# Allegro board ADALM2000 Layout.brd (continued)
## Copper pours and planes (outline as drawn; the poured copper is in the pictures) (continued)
-6V0_A on TOP: 42.9,16.46 42.9,17.35 43.79,17.35 43.79,20.01 48.74,20.01 48.74,18.11 46.89,18.11 46.89,18.72 45.59,18.72 45.59,18.11 45.57,18.11 45.57,16.46
-6V0_A on TOP: 51.03,11.12 57,11.12 57.76,10.36 58.9,10.36 58.9,14.04 58.39,14.04 57.76,13.41 51.03,13.41
-6V0_A on BOTTOM: 21.69,6.04 23.34,6.04 23.34,7.95 21.69,7.95
-6V0_A on BOTTOM: 24.61,40.21 24.61,37.92 24.99,37.92 25.12,37.79 27.28,37.79 27.28,38.68 27.66,39.06 27.66,40.21
-6V0_A on BOTTOM: 51.15,11.12 57,11.12 57.12,11.25 59.03,11.25 59.03,13.41 51.15,13.41
-6V0_A on L8_PWR: 13.94,5.53 13.94,41.09 27.91,41.09 27.91,27.19 21.05,27.19 21.05,14.68 33.31,14.68 33.31,20.77 51.59,20.77 57.12,15.25 57.12,10.3 41.43,10.3 39.85,8.71 25.06,8.71 25.06,5.53
-6V0_AWG_A on BOTTOM: 24.48,34.62 26.26,34.62 26.39,34.74 26.39,37.35 24.48,37.35
-6V0_AWG_A on L3_PWR: 22.83,27.76 22.83,36.33 33.63,36.33 33.63,27.76
-6V0_SC_A on TOP: 14.96,50.49 14.96,48.71 16.86,48.71 16.86,50.49
-6V0_SC_A on BOTTOM: 32,46.17 32,47.85 31.85,47.85 31.85,48.51 32.1,48.51 32.1,48.56 33.86,48.56 34.01,48.71 35.15,48.71 35.15,47.7 34.36,46.91 32.76,46.91 32.76,46.17
-6V0_SC_A on BOTTOM: 17.75,49.73 17.75,48.84 20.8,48.84 20.8,49.98 19.02,49.98 18.77,49.73
-6V0_SC_A on BOTTOM: 32.61,37.09 32.61,37.98 32.04,38.55 27.66,38.55 27.66,37.67 28.61,37.67 29.18,37.09
-6V0_SC_A on L3_PWR: 22.83,36.97 22.83,46.17 13.94,46.17 13.94,50.3 22.83,50.3 22.83,54.75 28.55,54.75 28.55,48.08 33.63,48.08 33.63,36.97
-6V0_USR_A on TOP (solid shape): 11.59,6.04 12.99,6.04 13,6.04 13.31,6.04 13.43,5.92 13.43,5.47 13.37,5.38 13.27,5.39 13.2,5.43 13.13,5.45 12.72,5.45 12.58,5.39 12.52,5.24 12.52,5.03 12.32,5.03 12.32,5.24 12.26,5.39 12.11,5.45 11.71,5.45 11.56,5.39 11.5,5.24 11.5,5.03 11.28,5.03 11.28,6.04 11.58,6.04
-6V0_USR_A on BOTTOM (solid shape): 13.82,4.9 13.54,4.9 13.54,5.33 13.48,5.47 13.33,5.53 12.77,5.53 12.63,5.47 12.57,5.33 12.57,4.9 12.39,4.9 12.39,5.33 12.33,5.47 12.19,5.53 11.63,5.53 11.49,5.47 11.43,5.33 11.43,4.9 11.15,4.9 11.15,6.04 13.82,6.04
-6V0_USR_A on BOTTOM: 19.91,6.04 21.31,6.04 21.31,7.69 19.91,7.69
-6V0_USR_A on L6_SIG: 10.77,4.9 21.56,4.9 21.56,8.58 10.77,8.58
GND on TOP: 95.1,45.67 95.1,48.41 95.2,48.41 95.2,48.89 94.79,48.89 94.71,48.97 94.71,49.73 93.83,49.73 93.83,53.29 97.38,53.29 97.38,49.73 96.49,49.73 96.49,48.71 96.43,48.65 96.43,49.71 96.02,49.71 96.02,48.39 96.24,48.39 96.24,45.67 ; 2 cut-outs
GND on TOP: outline of 92 points within 0.64,0.64 108.5,68.7 ; 150 cut-outs
GND on BOTTOM: 102.21,4.02 79.2,1.56 56.08,0.64 56.08,6.28 52.28,10.08 48.48,6.28 48.48,0.68 26.97,1.69 5.56,4.05 5.56,5.66 5.55,5.66 4.42,6.68 3.28,5.66 3.27,5.66 3.27,4.38 1.96,4.58 0.64,4.78 0.64,15.69 0.61,15.69 0.61,15.82 0.73,15.82 0.73,53.29 0.64,53.29 0.64,64.55 1.89,64.75 3.15,64.94 5.69,65.31 27.03,67.65 48.48,68.66 48.48,63.06 52.28,59.26 56.08,63.06 56.08,68.7 75.11,68.05 94.08,66.36 94.08,57.1 98.72,57.1 100.62,55.19 100.62,51.89 102.53,49.98 102.53,40.52 101.57,39.57 101.57,32.84 105.07,29.35 108.5,29.35 108.5,16.08 108.5,8.6 107.49,5.87 104.95,4.43 104.75,4.4 104.75,5.53 103.48,6.8 102.21,5.53 ; 182 cut-outs
GND on L2_GND: 104.08,4.29 80.14,1.63 56.08,0.64 56.08,6.28 52.28,10.08 48.48,6.28 48.48,0.68 24.49,1.9 0.64,4.78 0.64,64.55 24.49,67.44 48.48,68.66 48.48,63.06 52.28,59.26 56.08,63.06 56.08,68.7 75.11,68.05 94.08,66.36 94.08,57.1 98.72,57.1 100.62,55.19 100.62,51.89 102.53,49.98 102.53,40.52 101.57,39.57 101.57,36.01 104.32,36.01 104.32,34.11 101.57,34.11 101.57,32.84 105.07,29.35 108.5,29.35 108.5,15.52 108.5,8.6 107.49,5.87 104.95,4.43
GND on L3_PWR: 86.97,46.81 86.97,62.68 56.06,62.68 56.07,62.87 56.08,63.06 56.08,68.7 75.11,68.05 94.08,66.36 94.08,57.1 98.71,57.1 100.74,55.06 100.62,55.06 100.62,51.89 102.53,49.98 102.53,46.81
GND on L3_PWR: 38.14,1 19.33,2.38 0.64,4.78 0.64,64.55 24.49,67.44 48.48,68.66 48.48,65.22 33.95,65.22 33.95,60.14 13.31,60.14 13.31,45.54 22.2,45.54 22.2,27.76 15.85,27.76 15.85,5.85 38.14,5.85
GND on L3_PWR: 77.44,1.43 66.77,0.87 56.08,0.64 56.08,6.28 55.52,8.26 54,9.66 71.73,9.66 71.73,22.68 77.44,22.68
GND on L4_GND, L7_GND, L9_GND: 104.08,4.29 80.14,1.63 56.08,0.64 56.08,6.28 52.28,10.08 48.48,6.28 48.48,0.68 24.49,1.9 0.64,4.78 0.64,64.55 24.49,67.44 48.48,68.66 48.48,63.06 52.28,59.26 56.08,63.06 56.08,68.7 75.11,68.05 94.08,66.36 94.08,57.1 98.72,57.1 100.62,55.19 100.62,51.89 102.53,49.98 102.53,40.52 101.57,39.57 101.57,32.84 105.07,29.35 108.5,29.35 108.5,15.52 108.5,8.6 107.49,5.87 104.95,4.43
GND on L5_SIG: 108.5,8.6 107.49,5.87 104.95,4.43 104.08,4.29 80.14,1.63 56.08,0.64 56.08,6.28 52.28,10.08 48.48,6.28 48.48,0.68 39.45,0.94 30.43,1.44 20.37,2.27 10.34,3.41 5.48,4.06 0.64,4.78 0.64,9.98 1.12,9.98 1.12,13.92 0.64,13.92 0.64,64.55 24.49,67.44 48.48,68.66 48.48,63.06 52.28,59.26 56.08,63.06 56.08,68.7 75.11,68.05 94.08,66.36 94.08,57.1 98.72,57.1 100.62,55.19 100.62,51.89 102.53,49.98 102.53,40.52 101.57,39.57 101.57,32.84 105.07,29.35 108.5,29.35 108.5,19.82 ; 63 cut-outs
GND on L8_PWR: 48.48,0.68 24.49,1.9 0.64,4.78 0.64,64.55 24.49,67.44 48.48,68.66 48.48,63.06 52.28,59.26 56.08,63.06 56.08,68.7 67.72,68.43 79.35,67.77 79.35,61.41 59.98,61.41 55.03,56.46 55.03,52.33 66.33,52.33 66.33,46.17 49.5,46.17 49.5,57.1 45.19,61.41 20.93,61.41 20.93,41.73 13.31,41.73 13.31,4.9 25.69,4.9 25.69,8.07 40.11,8.07 41.7,9.66 50.55,9.66 49.04,8.26 48.48,6.28
PGND on TOP: 105,40.97 105,39.32 106.4,39.32 106.4,41.09 105.13,41.09
PGND on TOP: 105.7,58.94 105.7,59.19 106.59,60.08 106.59,60.91 106.65,60.97 108.49,60.97 108.49,58.94
PGND on TOP: 103.16,43.13 103.16,50.37 101.26,52.27 101.26,55.32 98.91,57.67 94.91,57.67 94.91,60.97 97.45,60.97 97.45,59.51 98.52,58.43 99.1,58.43 100.56,59.89 100.56,60.14 104.62,64.21 108.08,60.75 107.8,60.46 106.72,60.46 105.13,62.05 104.49,62.05 102.02,59.57 101.95,59.57 101.06,58.68 101.06,57.86 101.89,57.03 101.89,52.84 102.08,52.65 103.73,52.65 104.43,51.95 104.43,45.79 104.94,45.79 104.94,45.1 104.62,44.78 104.62,43.13
PGND on TOP: 102.84,32.46 103.73,32.46 104.11,32.84 104.11,33.6 102.97,33.6 102.72,33.35 102.72,32.59
PGND on BOTTOM: 105.38,29.92 102.72,32.59 102.72,33.6 105,33.6 105,37.67 104.49,38.17 104.49,40.08 104.75,40.33 104.75,41.73 105.45,42.43 106.91,42.43 106.91,46.11 106.65,46.37 105.89,46.37 105.64,46.11 104.37,46.11 104.3,46.05 104.3,43.13 103.16,43.13 103.16,50.3 101.26,52.21 101.26,55.32 98.91,57.67 94.91,57.67 94.91,65.22 102.72,65.22 106.84,61.1 107.41,61.1 108.49,60.02 108.49,55.89 106.65,55.89 106.65,55.51 106.46,55.32 106.46,48.21 107.16,47.51 108.43,47.51 108.43,39.82 106.97,39.82 106.46,39.32 106.46,29.92 ; 3 cut-outs
PGND on L2_GND: 103.16,40.14 103.16,50.3 101.26,52.21 101.26,55.32 98.91,57.67 94.91,57.67 94.91,65.22 102.72,65.22 106.84,61.1 107.41,61.1 108.49,60.02 108.49,55.89 106.65,55.89 106.65,55.37 106.54,55.11 106.5,54.82 106.81,54.07 107.56,53.76 107.61,53.76 107.61,51.13 107.56,51.13 106.81,50.82 106.5,50.07 106.81,49.32 107.56,49.01 108.43,49.01 108.43,39.82 106.97,39.82 106.46,39.32 106.46,29.92 105.38,29.92 102.72,32.59 102.72,33.6 105.7,33.6 105.7,36.27 105.07,36.9 102.21,36.9 102.21,39.19
PGND on L4_GND: 103.16,40.14 103.16,50.3 101.26,52.21 101.26,55.32 98.91,57.67 94.91,57.67 94.91,65.22 102.72,65.22 106.84,61.1 107.41,61.1 108.49,60.02 108.49,55.89 106.65,55.89 106.65,55.37 106.54,55.11 106.5,54.82 106.81,54.07 107.56,53.76 107.61,53.76 107.61,51.13 107.56,51.13 106.81,50.82 106.5,50.07 106.81,49.32 107.56,49.01 108.43,49.01 108.43,39.82 106.97,39.82 106.46,39.32 106.46,29.92 105.38,29.92 102.72,32.59 102.72,33.6 105,33.6 105,36.07 104.16,36.9 102.21,36.9 102.21,39.19
PGND on L7_GND, L9_GND: 103.16,40.14 103.16,50.3 101.26,52.21 101.26,55.32 98.91,57.67 94.91,57.67 94.91,65.22 102.72,65.22 106.84,61.1 107.41,61.1 108.49,60.02 108.49,55.89 106.65,55.89 106.65,55.37 106.54,55.11 106.5,54.82 106.81,54.07 107.56,53.76 107.61,53.76 107.61,51.13 107.56,51.13 106.81,50.82 106.5,50.07 106.81,49.32 107.56,49.01 108.43,49.01 108.43,39.82 106.97,39.82 106.46,39.32 106.46,29.92 105.38,29.92 102.72,32.59 102.72,33.6 105,33.6 105,36.07 104.16,36.9 102.21,36.9 102.21,39.19
VCCPINT on TOP: 80.87,44.78 80.87,43.63 83.03,41.48 84.55,41.48 84.55,44.52 84.3,44.78
VCCPINT on BOTTOM: 84.55,47.32 84.55,43.63 84.05,43.13 84.05,41.09 81.95,41.09 80.87,42.17 80.87,45.54 81.38,46.05 81.38,47.32
VCCPINT on L3_PWR: 71.73,23.31 71.73,46.17 91.73,46.17 91.73,34.24 88.56,31.07 88.56,27.26 84.61,23.31
VIN on TOP: 93.19,50.87 93.19,49.35 92.81,48.97 89.25,48.97 89.25,50.87 ; 1 cut-out
VIN on TOP: 83.41,51.38 84.43,51.38 84.81,51.76 88.11,51.76 88.11,53.16 82.78,53.16 82.78,52.02
VIN on TOP: 99.55,31.56 98.78,32.33 97.7,32.33 97.7,31.63 98.66,30.67
VIN on TOP: 97.89,50.87 101.57,50.87 102.21,50.24 102.21,48.97 98.4,48.97 97.89,49.48 ; 1 cut-out
VIN on TOP: 78.33,51.38 77.7,51.38 77.32,51.76 73.12,51.76 73.12,53.16 78.97,53.16 78.97,52.02
VIN on TOP: 85.44,63.57 86.33,62.68 91.29,62.68 91.67,62.3 93.95,62.3 93.95,65.22 87.48,65.22 86.59,66.11 83.28,66.11 83.28,63.57
VIN on L6_SIG: 106.65,22.68 97.13,32.2 97.13,48.71 97.76,49.35 97.76,51.25 101.19,51.25 102.21,50.24 102.21,47.38 99.29,47.38 99.29,42.11 101.57,39.82 101.57,32.84 105.07,29.35 108.3,29.35 108.3,9.79 106.65,9.79
VIN on L8_PWR: 82.84,48.71 82.84,51.57 73.32,51.57 73.32,54.75 66.33,54.75 66.33,52.97 55.66,52.97 55.66,56.21 60.23,60.78 79.98,60.78 79.98,65.61 90.33,65.61 94.08,61.86 94.08,57.1 98.72,57.1 100.62,55.19 100.62,51.91 102.53,50.01 102.53,48.71
VIN_5V_USB_DATA on TOP: 105.13,59.51 103.73,60.91 104.56,61.73 104.94,61.73 106.14,60.53 106.14,60.21 105.45,59.51 ; 2 cut-outs
VIN_5V_USB_DATA on TOP: 102.33,36.71 102.33,39.32 103.22,40.21 104.75,40.21 104.75,38.55 103.73,37.54 103.73,36.97 103.86,36.84 103.86,35.76 103.29,35.76
VIN_5V_USB_DATA on BOTTOM: 103.99,38.94 103.99,37.03 103.48,36.52 102.33,36.52 102.33,38.17 103.1,38.94
VIN_5V_USB_DATA on L8_PWR: 102.21,36.65 102.21,39.06 103.16,40.01 103.16,50.27 101.26,52.17 101.26,58.43 103.92,61.1 107.41,61.1 108.5,60.01 108.5,57.47 108.5,55.88 107.56,55.88 106.81,55.57 106.5,54.82 106.81,54.07 107.56,53.76 108.5,53.76 108.5,51.13 107.56,51.13 106.81,50.82 106.5,50.07 106.81,49.32 107.56,49.01 108.5,49.01 108.5,38.1 107.56,38.1 106.81,37.79 106.5,37.04 106.52,36.84 106.58,36.65
VIN_5V_USB_POWER on TOP: 102.21,53.16 102.21,57.35 101.38,58.18 101.38,58.56 102.14,59.32 102.21,59.32 104.05,57.48 104.05,53.67 103.54,53.16 ; 2 cut-outs
VIN_5V_USB_POWER on TOP: 104.87,46.11 106.78,46.11 106.78,47.38 105.38,47.38 104.87,46.87
VIN_5V_USB_POWER on BOTTOM: 102.21,54.18 103.54,54.18 103.54,55.51 102.21,55.51
VIN_5V_USB_POWER on L3_PWR: 105.32,29.98 102.72,32.59 102.72,33.6 104.94,33.6 104.94,36.65 102.21,36.65 102.21,39.06 103.16,40.01 103.16,50.24 101.26,52.15 101.26,55.7 101.01,55.7 98.97,57.73 94.71,57.73 94.71,66.29 99.4,65.7 104.08,65.04 104.95,64.9 107.49,63.47 108.5,60.73 108.5,57.47 108.5,55.88 107.56,55.88 106.81,55.57 106.5,54.82 106.81,54.07 107.56,53.76 108.5,53.76 108.5,51.13 107.56,51.13 106.81,50.82 106.5,50.07 106.81,49.32 107.56,49.01 108.5,49.01 108.5,38.1 107.56,38.1 106.81,37.79 106.5,37.04 106.81,36.29 107.56,35.98 108.5,35.98 108.5,33.35 107.56,33.35 106.81,33.04 106.5,32.29 106.81,31.54 107.56,31.23 108.5,31.23 108.5,29.98
(no net) on TOP: 13.43,5.03 11.28,5.03 11.28,6.04 13.31,6.04 13.43,5.92
(no net) on TOP: 15.72,12.01 19.98,12.01 19.98,13.47 15.72,13.47
(no net) on TOP: 13.69,11.12 11.66,11.12 11.66,12.14 13.43,12.14 13.69,11.88
(no net) on TOP: 15.72,6.3 18.51,6.3 18.51,7.57 15.72,7.57
(no net) on BOTTOM: 10.77,11 13.94,11 13.94,12.27 10.77,12.27
(no net) on BOTTOM: 16.36,6.42 18.9,6.42 18.9,7.57 16.36,7.57
(no net) on BOTTOM: 11.15,4.9 13.82,4.9 13.82,6.04 11.15,6.04
(no net) on BOTTOM: 16.61,12.01 18.9,12.01 18.9,13.28 16.74,13.28 16.36,12.9 16.36,12.27
(no net) on L6_SIG: outline of 252 points within 0.64,0.64 108.5,68.7 ; 11 cut-outs
REF_1V2 on BOTTOM: 33.95,24.08 31.21,24.08 31.21,26.36 32.23,26.36 32.48,26.62 33.95,26.62
REF_1V2_SC on BOTTOM: 41.37,23.31 41.37,25.35 40.49,25.35 40.49,26.49 38.83,26.49 38.83,25.35 38.33,25.35 38.33,23.31
UNNAMED_16_ADP5074_I189_SW on TOP: 56.11,17.98 65.63,17.98 65.63,12.77 62.71,12.77 62.71,15.06 58.01,15.06 56.11,16.96
UNNAMED_16_ADP7182V2_I221_VOUT on TOP: 43.28,18.11 41.25,18.11 41.25,20.52 43.28,20.52
UNNAMED_16_CAP_I199_N1 on TOP: 59.41,10.36 62.2,10.36 62.2,14.3 59.41,14.3
UNNAMED_37_ADP237X_I231_SW on TOP: 36.04,2.23 36.04,9.85 36.93,10.74 37.18,10.74 37.95,9.98 39.09,9.98 39.09,2.23
UNNAMED_37_ADP1614_I262_SW1 on TOP: 40.61,7.57 40.61,1.98 42.52,1.98 42.52,6.17 45.06,6.17 45.57,6.68 45.57,7.57
UNNAMED_37_CAP_I212_N1 on TOP: 32.61,13.41 32.61,20.01 29.94,20.01 29.94,15.44 28.67,15.44 28.67,13.41
UNNAMED_37_CAP_I212_N1 on BOTTOM: 32.61,14.81 30.33,14.81 30.33,20.65 32.61,20.65
UNNAMED_37_CAP_I222_N2 on TOP: 34.52,2.23 30.71,2.23 30.71,8.46 28.55,10.61 28.55,12.14 34.52,12.14
UNNAMED_37_CAP_I315_N1 on TOP: 43.41,10.04 40.36,10.04 40.36,12.9 42.14,12.9 42.14,12.46 43.41,11.19
UNNAMED_38_ADP2114_I358_SW1 on TOP: 96.75,49.54 97.31,49.54 98.52,48.33 98.52,42.62 96.75,42.62 ; 1 cut-out
UNNAMED_38_ADP2114_I358_SW3 on TOP: 94.46,42.62 92.81,42.62 92.81,48.42 93.61,49.22 94.46,49.22
UNNAMED_38_ADP2114_I447_SW1 on TOP: 82.01,51.76 82.01,45.29 83.67,45.29 83.67,50.75 82.65,51.76
UNNAMED_38_ADP2114_I447_SW3 on TOP: 79.73,51.51 79.73,49.73 79.98,49.48 79.98,47.44 75.92,47.44 75.92,48.59 76.43,49.1 78.33,49.1 78.33,51 78.84,51.51
UNNAMED_38_CAP_I379_N1 on TOP: 101.83,46.3 99.41,46.3 99.41,41.09 101.83,41.09
UNNAMED_38_CAP_I379_N1 on BOTTOM: 99.41,39.95 101.95,39.95 102.46,40.46 102.46,44.14 99.41,44.14
UNNAMED_38_CAP_I457_N1 on TOP: 73.38,43.76 76.3,43.76 77.19,44.65 79.35,44.65 79.98,45.29 79.98,46.68 76.05,46.68 75.54,47.19 73.38,47.19
UNNAMED_38_CAP_I457_N1 on BOTTOM: 73.38,43.76 76.68,43.76 76.68,47.01 73.38,47.01
UNNAMED_45_ADP198_I317_VOUT on TOP: 103.22,41.6 103.22,42.62 105.13,42.62 105.13,45.79 106.78,45.79 106.78,41.6
UNNAMED_45_ADP198_I317_VOUT on BOTTOM: 104.68,43 106.53,43 106.53,45.73 104.68,45.73
UNNAMED_45_CAP_I416_N1 on TOP: 98.65,58.87 100.65,60.87 99.92,61.61 99.92,61.8 101.19,63.07 101.57,63.07 102.21,62.43 104.11,64.34 103.35,65.1 102.84,65.1 102.72,65.22 94.84,65.22 94.91,64.94 94.91,62.11 97.25,62.11 97.89,61.48 97.89,59.64 ; 4 cut-outs
UNNAMED_45_CN5P3SHLD_I255_N6 on TOP: 106.02,30.17 106.02,36.33 105.76,36.59 105.76,38.68 106.65,39.57 106.65,40.97 107.92,40.97 107.92,40.08 108.5,39.5 108.5,38.1 107.56,38.1 106.81,37.79 106.5,37.04 106.81,36.29 107.56,35.98 108.5,35.98 108.5,33.35 107.56,33.35 106.81,33.04 106.5,32.29 106.81,31.54 107.56,31.23 108.5,31.23 108.5,30.28 108.3,30.28 108.3,30.17
UNNAMED_45_CN5P3SHLD_I256_N6 on TOP: 108.5,58.49 108.5,55.88 107.56,55.88 106.81,55.57 106.5,54.82 106.81,54.07 107.56,53.76 108.5,53.76 108.5,51.13 107.56,51.13 106.81,50.82 106.5,50.07 106.81,49.32 107.56,49.01 108.43,49.01 108.43,47.95 106.02,47.95 106.02,54.94 105.7,55.26 105.7,58.49
USB_VBUS_OTG on TOP: 99.41,39.44 99.41,37.6 101.76,37.6 101.76,39.44
USB_VBUS_OTG on BOTTOM: 99.16,38.3 99.67,37.79 101.32,37.79 102.21,38.68 102.21,38.94 99.54,38.94 99.16,38.55
VTT_0P75 on TOP: 102.3,28.75 103.92,27.13 104.9,28.12 103.02,30.01 102.39,29.38 102.66,29.11
VTT_0P75 on BOTTOM: 104.62,18.36 98.82,24.16 93.64,18.99 94.63,18 98.53,21.89 101.74,18.67 100.08,17.01 99.18,17.01 97.44,15.26 99.2,13.51 100.79,15.1 100.79,16.09 101.4,16.7 103.57,16.7 104.55,15.73 104.31,15.5 105.03,14.78 103.27,13.02 102.91,13.02 99.23,9.34 99.95,8.62 101.03,8.62 103.81,11.4 105.07,11.4 107.67,14 107.67,26.49 105.76,28.39 103.99,28.39 103.16,29.22 102.33,28.39 102.33,27.38 105.38,24.33 105.38,18.62 105.13,18.36

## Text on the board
Board Geometry/Soldermask Bottom: SOLDERMASK SECONDARY | 08-      -06
Ref Des/Silkscreen Bottom: SECONDARY SIDE | SILKSCREEN SECONDARY | 08-      -05
User.Comments: CR_1_1 | 5.    DS11 AND DS12 ARE RIGHT ANGLE LEDs
TOP: ADALM-2000
Ref Des/Assembly Top: K | A
Board Geometry/Soldermask Top: SOLDERMASK PRIMARY | 08-      -04
Ref Des/Silkscreen Top: K | A | PRIMARY SIDE | 08-042233 REV D Z | SILKSCREEN PRIMARY | 08-      -03
ROOT_NUMBER: 042233 | REV D
DIMENSION: " " | SEE DETAIL A | (2 PLACES) | 2.486 | 2.320 | 2.240 | .004 | 0 | 4.297 | R13.599 | 1.932 | 1.899 | 1.745 | 1.712 | 1.232 | 1.199 | 1.045 | 1.012 | R.191 | 0.0330 | (2PLCS) | 0.0165 | 0.0395 | 0.0790 | RADIUS | FULL | SCALE: NONE | DETAIL A | 0.1870 | EDGE | PCB | (2x) | REF | BOARD DIMENSIONS | ARRAY DIMENSIONS | x2 | FIDUCIAL | TOOLING HOLE (4X) | MOLEX47590-0001_CUTOUT-DETAIL | DIA MAX | SEE NOTE #15 | -1.074 | .860 | .984 | 1.109 | 3.223 | 2.730
PAGE_OUTLINE: B | C | D | AS PER ECR-068314 | AS PER ECR-070284 | AS PER ECR-077228 | 26APR17 | 23SEP17 | 04OCT18 | MBANCISOR | CUSTOMER EVAL BOARD Z
DISPLAY_BOTTOM: L1 PRIMARY | 08-      -01
DISPLAY_TOP: L10 SECONDARY | 08-      -02
User.9: PASTEMASK PRIMARY | 08-      -15
User.10: PASTEMASK SECONDARY | 08-      -16
User.15: PREPREG 2.98MILS | PREPREG 2.9MILS | CORE 3MILS | NOTE: ALL IMPEDANCE TOLERANCE +/-10% | LAYER | L1 | L5 | L6 | L10 | SE = SINGLE ENDED, DP = DIFFERENTIAL PAIR | 100 OHMS DP | IMPEDANCE | 50 OHMS SE | 40 OHMS SE | 90 OHMS DP | 80 OHMS DP | REFERENCE | L4,L7 | L2 | L4 | L9 | LINE WIDTH | 4.01MILS | 4.02MILS | 19MILS | 6.5MILS | 4MILS | 9MILS | 4.5MILS | 5.5MILS | 5MILS | SPACE | 7MILS | 6MILS | N/A | IMPEDANCE TABLE
User.17: L2 GND | 08-      -07
User.18: L3 PWR | 08-      -08
User.19: L4 GND | 08-      -09
User.20: L5 SIG | 08-      -10
User.22: L6 SIG | 08-      -11
User.23: L7 GND | 08-      -12
User.24: L8 PWR | 08-      -13
User.25: L9 GND | 08-      -14
User.45: FIGURE | SIZE | 8.0 | 10.0 | 10.01 | 28.0 | 30.0 | 45.0 | 25.0 | 50.0 | 126.0 | 34.0x26.0 | 51.0x24.0 | FINISHED HOLES IN MILS | ALL UNITS ARE IN MILS | PLATED | NON-PLATED | QTY | 498 | 1294 | 371 | 10 | 8 | 30 | 18 | 2 | 12 | 4 | TOLERANCE/NOTES
